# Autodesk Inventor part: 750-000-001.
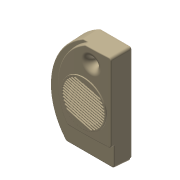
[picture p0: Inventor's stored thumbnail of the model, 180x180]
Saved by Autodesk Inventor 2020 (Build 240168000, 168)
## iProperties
Created: 2010-12
Part Number: 750-000-001.
Document SubType Name: Modeling
Designer: F.Stasiak
Density: 1.06 g/cm^3
Material: Tworzywo sztuczne ABS
Appearance: Beżowa
Mass: 166.261 g
Surface Area: 1085.8 cm^2
Volume: 156.85 cm^3
Manager: www.cadconsulting.pl
Company: Fabian Stasiak CAD Consulting
Author: F.Stasiak
Subject: Zbiór ćwiczeń. Autodesk Inventor 2020. Kurs podstawowy
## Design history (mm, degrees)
sketch "Szkic1"
  geometry: L1 (0, 0)-(0, 200); L2 (0, 200)-(-65, 200); L3 (0, 0)-(-100, 0); A1 r 130 centre (-2.514, 86.002) between (-65, 200) and (-100, 0)
  constraints: 6 end point, 2 point on circle, 1 centre point, 1 parallel, 1 perpendicular, 1 vertical
  dimensions: "d0" = 200 distance of L1.start L1.end; "d1" = 65 distance of L1.end L2.end; "d2" = 100 distance of L1.start L3.end; "d3" = 130 radius of A1
extrude "Wyciągnięcie proste1" new body sketch "Szkic1" distance "d4" = 30; taper "d5" = 0 deg
sketch "Szkic3"
  geometry: L1 (0, 0)-(-100, 0) reference; L2 (0, 200)-(0, 0) reference; L3 (-65, 200)-(0, 200) reference; L4 (0, 38.775)-(-90, 38.775); A1 r 130 centre (-2.514, 86.002) between (-65, 200) and (-100, 0) reference; A2 r 110 centre (0, 102.02) between (-50, 200) and (-90, 38.775); 1 further point
  constraints: 3 point on line, 2 end point, 2 point on circle, 1 centre point, 1 parallel
  dimensions: "d11" = 90 distance of L4.start L4.end; "d12" = 50 distance from line of L2 A2.start; "d13" = 110 radius of A2
extrude "Wyciągnięcie proste2" join sketch "Szkic3" distance "d14" = 8; taper "d15" = 0 deg
feature "Pochylenie ściany1" dims angle "d16" = 2.5 deg
feature "Pochylenie ściany2" dims angle "d17" = 2.5 deg
sketch "Szkic2"
  geometry: A1 r 900 centre (62.935, -861.801) between (144.257, 34.518) and (-4.9, 35.639); 1 further point
  constraints: 2 point on circle, 1 centre point
  dimensions: "d90" = 900 radius of A1
feature "PowWyciągnięciaProstego1" sketch "Szkic2" dims "d6" = 210, "d7" = 0
feature "Wydłuż2" dims "d18" = 10
node "Płaszczyzna konstrukcyjna2"
sketch "Szkic5"
  geometry: L1 (40, 0)-(40, 38); L2 (0, 0)-(65, 0) reference; L3 (52.399, 38)-(109.651, 38) reference; L4 (46, 0)-(46, 20); L5 (52.399, 38)-(1.659, 38) reference; L6 (57.282, 38)-(40, 38); L7 (46, 0)-(40, 0); A1 r 20 centre (66, 20) between (57.282, 38) and (46, 20); 1 further point
  constraints: 8 end point, 4 point on line, 2 point on circle, 1 centre point, 1 collinear, 1 parallel, 1 perpendicular, 1 tangent, 1 vertical
  dimensions: "d26" = 20 radius of A1; "d27" = 12 diameter of L4 L1; "d28" = 20 distance of L4.start L4.end; "d29" = 40 distance from line of L2.start L1
revolve "Obrót1" sketch "Szkic5" stored, may be unused: angle "d30" = 90 deg
feature "Zamień powierzchnię4"
fillet "Zaokrąglenie3" dims "d19" = 5
fillet "Zaokrąglenie4" dims "d20" = 2
feature "Skorupa1" dims "d22" = 3.5, "d32" = 2
fillet "Zaokrąglenie6" dims "d23" = 1
fillet "Zaokrąglenie8" dims "d33" = 10
node "Płaszczyzna konstrukcyjna1"
fillet "Zaokrąglenie9" dims "d86" = 1
feature "Przesunięcie powierzchni1"
sketch "Szkic7"
  geometry: L1 (3.503, 5.002)-(3.503, 194.998) reference; L2 (5.002, 196.497)-(63.706, 196.497) reference; L3 (97.716, 3.503)-(5.002, 3.503) reference; L4 (34.354, 196.497)-(34.354, 188.497); L5 (3.503, 181.497)-(11.503, 181.497); L6 (85.473, 181.497)-(77.473, 181.497); L7 (3.503, 166.497)-(15.503, 166.497); L8 (100.095, 166.497)-(75.095, 166.497); L9 (3.503, 100)-(9.503, 100); L10 (127.031, 108.292)-(119.031, 108.292); L11 (3.503, 136.497)-(11.503, 136.497); L12 (118.495, 136.497)-(110.495, 136.497); L13 (3.503, 23.503)-(18.503, 23.503); L14 (112.492, 23.503)-(92.492, 23.503); L15 (3.503, 63.503)-(11.503, 63.503); L16 (126.993, 63.503)-(118.993, 63.503); L17 (18.503, 3.503)-(18.503, 23.503); L18 (92.492, 23.503)-(92.492, 3.503); A1 r 126.497 centre (2.514, 86.002) between (98.857, 4.031) and (64.439, 196.305) reference; 1 further point
  constraints: 30 end point, 10 collinear, 7 point on line, 6 parallel, 6 point on circle, 4 perpendicular, 2 midpoint
  dimensions: "d95" = 8 distance of L4.start L4.end; "d96" = 8 distance of L5.start L5.end; "d97" = 8 distance of L6.start L6.end; "d98" = 12 distance of L7.start L7.end; "d99" = 15 distance between parallel lines of L5 L2; "d100" = 30 distance between parallel lines of L7 L2; "d101" = 25 distance of L8.start L8.end; "d102" = 6 distance of L9.start L9.end; "d103" = 8 distance of L10.start L10.end; "d104" = 8 distance of L11.start L11.end; "d105" = 8 distance of L12.start L12.end; "d106" = 60 distance between parallel lines of L11 L2; "d107" = 15 distance of L13.start L13.end; "d108" = 20 distance of L14.start L14.end; "d109" = 20 distance between parallel lines of L13 L3; "d110" = 8 distance of L15.start L15.end; "d111" = 8 distance of L16.start L16.end; "d112" = 60 distance between parallel lines of L3 L15
feature "Żebro1" sketch "Szkic7" dims "d115" = 1, "d116" = 1, "d117" = 0.5 deg
fillet "Zaokrąglenie10" dims "d118" = 2
sketch "SZKIC KRATKI"
  geometry: L1 (0, 4.995)-(0, 195.005) reference; L2 (-97.719, 0)-(-4.995, 0) reference; L3 (-96.052, 106)-(-13.948, 84); L4 (-60.5, 74.474)-(-49.5, 115.526); L5 (-94.758, 110.829)-(-12.654, 88.83); L6 (-93.464, 115.659)-(-11.36, 93.659); L7 (-92.17, 120.489)-(-10.066, 98.489); L8 (-90.875, 125.318)-(-8.772, 103.319); L9 (-89.581, 130.148)-(-7.478, 108.148); L10 (-88.287, 134.978)-(-6.184, 112.978); L11 (-97.346, 101.17)-(-15.242, 79.171); L12 (-96.052, 106)-(-13.948, 84); L13 (-94.758, 110.829)-(-12.654, 88.83); L14 (-93.464, 115.659)-(-11.36, 93.659); L15 (-92.17, 120.489)-(-10.066, 98.489); L16 (-90.875, 125.318)-(-8.772, 103.319); L17 (-89.581, 130.148)-(-7.478, 108.148); L18 (-98.64, 96.341)-(-16.536, 74.341); L19 (-97.346, 101.17)-(-15.242, 79.171); L20 (-96.052, 106)-(-13.948, 84); L21 (-94.758, 110.829)-(-12.654, 88.83); L22 (-93.464, 115.659)-(-11.36, 93.659); L23 (-92.17, 120.489)-(-10.066, 98.489); L24 (-90.875, 125.318)-(-8.772, 103.319); L25 (-99.934, 91.511)-(-17.83, 69.511); L26 (-98.64, 96.341)-(-16.536, 74.341); L27 (-97.346, 101.17)-(-15.242, 79.171); L28 (-96.052, 106)-(-13.948, 84); L29 (-94.758, 110.829)-(-12.654, 88.83); L30 (-93.464, 115.659)-(-11.36, 93.659); L31 (-92.17, 120.489)-(-10.066, 98.489); L32 (-101.228, 86.681)-(-19.125, 64.682); L33 (-99.934, 91.511)-(-17.83, 69.511); L34 (-98.64, 96.341)-(-16.536, 74.341); L35 (-97.346, 101.17)-(-15.242, 79.171); L36 (-96.052, 106)-(-13.948, 84); L37 (-94.758, 110.829)-(-12.654, 88.83); L38 (-93.464, 115.659)-(-11.36, 93.659); L39 (-102.522, 81.852)-(-20.419, 59.852); L40 (-101.228, 86.681)-(-19.125, 64.682); L41 (-99.934, 91.511)-(-17.83, 69.511); L42 (-98.64, 96.341)-(-16.536, 74.341); L43 (-97.346, 101.17)-(-15.242, 79.171); L44 (-96.052, 106)-(-13.948, 84); L45 (-94.758, 110.829)-(-12.654, 88.83); L46 (-103.816, 77.022)-(-21.713, 55.022); L47 (-102.522, 81.852)-(-20.419, 59.852); L48 (-101.228, 86.681)-(-19.125, 64.682); L49 (-99.934, 91.511)-(-17.83, 69.511); L50 (-98.64, 96.341)-(-16.536, 74.341); L51 (-97.346, 101.17)-(-15.242, 79.171); L52 (-96.052, 106)-(-13.948, 84); L53 (-86.993, 139.807)-(-4.889, 117.808); L54 (-88.287, 134.978)-(-6.184, 112.978); L55 (-89.581, 130.148)-(-7.478, 108.148); L56 (-90.875, 125.318)-(-8.772, 103.319); L57 (-92.17, 120.489)-(-10.066, 98.489); L58 (-93.464, 115.659)-(-11.36, 93.659); L59 (-94.758, 110.829)-(-12.654, 88.83); L60 (-105.111, 72.192)-(-23.007, 50.193); L61 (-103.816, 77.022)-(-21.713, 55.022); L62 (-102.522, 81.852)-(-20.419, 59.852); L63 (-101.228, 86.681)-(-19.125, 64.682); L64 (-99.934, 91.511)-(-17.83, 69.511)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; C1 r 40 at (-55, 95); A1 r 42.5 centre (-55, 95) between (-96.052, 106) and (-13.948, 84); 65 further points
  constraints: 130 end point, 2 centre point, 2 midpoint, 2 point on circle, 1 coincident, 1 concentric, 1 perpendicular, 254 other
  dimensions: "d34" = 85 diameter of A1; "d35" = 55 distance from line of L1 A1.centre; "d36" = 95 distance from line of L2 A1.centre; "d37" = 15 deg angle of L3 L2; "d38" = 42.5 distance of L4.start L4.end (= 0.5 x d34); "d41" = 5 distance of L3.start L5.start; "d44" = 5 distance of L3.start L11.start; "d77" = 80 diameter of C1
node "Płaszczyzna konstrukcyjna4"
node "Płaszczyzna konstrukcyjna5"
sketch "SZKIC MONTAŻU GŁOŚNIKA"
  geometry: L1 (-21.459, 128.541)-(-88.541, 128.541); L2 (-88.541, 128.541)-(-88.541, 61.459); L3 (-88.541, 61.459)-(-21.459, 61.459); L4 (-21.459, 61.459)-(-21.459, 128.541); C1 r 42.5 at (-55, 95) reference; A1 r 47.435 centre (-55, 95) between (-21.459, 128.541) and (-88.541, 128.541); 4 further points
  constraints: 8 end point, 5 coincident, 3 point on circle, 2 parallel, 2 perpendicular, 1 centre point, 1 horizontal
sketch "SZKIC KOMINKÓW MONTAŻOWYCH"
  geometry: L1 (75.095, 166.997)-(75.095, 165.997) reference; L2 (15.503, 165.997)-(15.503, 166.997) reference; L3 (3.503, 23.003)-(18.003, 23.003) reference; L4 (19.003, 3.503)-(19.003, 24.003) reference; L5 (18.003, 23.003)-(19.003, 24.003); L6 (92.992, 23.003)-(112.207, 23.003) reference; L7 (91.992, 24.003)-(91.992, 3.503) reference; L8 (92.992, 23.003)-(91.992, 24.003); 5 further points
  constraints: 4 end point, 4 midpoint, 1 perpendicular, 1 point on line
feature "Kratka3" dims "d190" = 5.5, "d191" = 2, "d192" = 3, "d193" = 4, "d194" = 0, "d195" = 2, "d196" = 2, "d197" = 0, "d198" = 10, "d199" = 0, "d200" = 1.5 deg, "d201" = 0, "d202" = 231.89703
feature "Pogrubienie5" dims "d203" = 2, "d204" = 2
feature "Pogrubienie6" dims "d205" = 2, "d206" = 2
feature "Kominek3" dims "d207" = 0, "d208" = 6.6, "d209" = 2.8, "d210" = 6, "d211" = 2 deg, "d212" = 1 deg, "d215" = 2, "d216" = 2, "d217" = 10, "d218" = 0, "d219" = 10 deg, "d220" = 2.5 deg, "d221" = 0, "d222" = 0, "d223" = 0, "d261" = 0, "d262" = 360 deg
feature "Kominek4" dims "d224" = 0, "d225" = 5, "d226" = 2.5, "d227" = 15, "d228" = 2 deg, "d229" = 1 deg, "d232" = 1, "d233" = 20, "d234" = 5, "d235" = 0, "d236" = 2 deg, "d237" = 0, "d238" = 0, "d239" = 0, "d240" = 0, "d263" = 0, "d264" = 360 deg
feature "Występ2" dims "d241" = 4, "d242" = 1.9, "d243" = 0, "d244" = 0, "d245" = 2.5 deg, "d246" = 0.25
feature "Reguła zaokrąglania17" dims "d255" = 1
feature "Reguła zaokrąglania18" dims "d256" = 0.75
feature "Reguła zaokrąglania21" dims "d260" = 0.5
node "Bryła1"
body "Srf1"
node "Pętla rzutowana1"
other parameters: "d24" = 45, "d119" = 12, "d188" = 2
